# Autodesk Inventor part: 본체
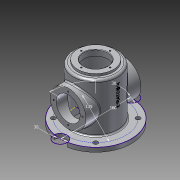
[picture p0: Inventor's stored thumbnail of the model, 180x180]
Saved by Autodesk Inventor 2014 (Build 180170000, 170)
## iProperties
Created: 2018-04
Part Number: 본체
Material: 알루미늄 6061
Document SubType Name: Modeling
Designer: NET
Density: 2.71 g/cm^3
Appearance: 알루미늄 - 평지
Mass: 1154.35 g
Surface Area: 1215.52 cm^2
Volume: 425.961 cm^3
Author: NET
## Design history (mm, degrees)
sketch "스케치1"
  geometry: L1 (-40, 65)-(-40, 60); L2 (-40, 60)-(-45, 60); L3 (-50, 55)-(-50, -68); L4 (-50, -68)-(0, -68); L5 (-40, 65)-(-27, 65); L6 (-27, 65)-(-27, 52); L7 (0, 65)-(0, -68); L8 (-27, 52)-(0, 52); A1 r 5 centre (-45, 55) between (-45, 60) and (-50, 55); 3 further points
  constraints: 16 end point, 5 point on line, 2 coincident, 2 horizontal, 2 perpendicular, 2 point on circle, 2 tangent, 1 centre point, 1 horizontal alignment, 1 parallel, 1 vertical
  dimensions: "d4" = 5 distance between parallel lines of L5 L2; "d5" = 133 distance between parallel lines of L4 L5; "d8" = 5 radius of A1; "d13" = 68 distance of L7.end point (0, 0); "d15" = 100 diameter of L3 L7; "d16" = 54 diameter of L6 L7; "d17" = 80 diameter of L1 L7; "d24" = 13 distance of L5.end L6.end
sketch "스케치2"
  geometry: L1 (-62, 0)-(62, 0); L2 (-62, 0)-(-62, 40); L3 (-62, 40)-(62, 40); L4 (62, 40)-(62, 0); 2 further points
  constraints: 8 end point, 2 perpendicular, 1 coincident, 1 horizontal, 1 midpoint, 1 vertical
  dimensions: "d22" = 124 distance of L2.end L3.end; "d23" = 80 diameter of L3 L1
revolve "회전3" stored, may be unused: angle "d25" = 90 deg
revolve "회전4" stored, may be unused: angle "d26" = 90 deg
sketch "스케치3"
  geometry: C1 r 50 at (0, 0) reference; C2 r 45 at (0, 0)
  constraints: 1 centre point, 1 coincident
  dimensions: "d27" = 90 diameter of C2
extrude "돌출1" cut sketch "스케치3" distance "d28" = 120; taper "d29" = 0 deg
fillet "모깎기1" dims "d30" = 3
sketch "스케치4"
  geometry: C1 r 40 at (0, 0) reference; C2 r 27 at (0, 0); 1 further point
  constraints: 1 centre point, 1 coincident, 1 vertical alignment
  dimensions: "d31" = 54 diameter of C2; "d34" = 32.5 distance of C1.centre point (0, 32.5)
extrude "돌출2" cut sketch "스케치4" stored distance "d32" = 120; taper "d33" = 0 deg
hole "구멍1" sketch "스케치4" diameter "d35" = 3.242; stored, may be unused: countersink angle "d39" = 90 deg, drill point angle "d41" = 118 deg; dims "d36" = 8, "d37" = 4, "d38" = 2, "d40" = 10
sketch "스케치5"
  geometry: C1 r 40 at (0, 0) reference; 1 further point
  constraints: 1 vertical alignment
  dimensions: "d45" = 32.5 distance of C1.centre point (0, 32.5)
hole "구멍2" sketch "스케치5" at (0, 32.5) diameter "d46" = 3.242; stored, may be unused: countersink angle "d50" = 90 deg, drill point angle "d52" = 118 deg; dims "d47" = 8, "d48" = 4, "d49" = 2, "d51" = 10
chamfer "모따기3" distance "d56" = 1; stored, may be unused: second distance "d57" = 2, angle "d58" = 45 deg
node "작업 평면1"
sketch "스케치6" dims "d89" = 135
  geometry: L1 (-47.73, 47.73)-(0, 0); L2 (0, 0)-(-80, 0); C1 r 50 at (0, 0) reference; C2 r 46 at (0, 0) reference; C3 r 15 at (0, 80); C4 r 15 at (0, -80); A1 r 80 centre (0, 0) between (0, 80) and (0, -80); 1 further point
  constraints: 4 end point, 3 centre point, 3 point on circle, 2 coincident, 2 vertical alignment, 1 horizontal, 3 other
  dimensions: "d60" = 160 diameter of A1; "d85" = 30 diameter of C3; "d86" = 30 diameter of C4; "d90" = 45 deg angle of L2 L1
  node "투영된 루프1"
extrude "바닥" join sketch "스케치6" distance "d64" = 10; taper "d65" = 0 deg
fillet "모깎기2" dims "d80" = 3
node "작업 평면2"
sketch "스케치8"
  geometry: L1 (0, -50)-(80, -50) reference; 2 further points
  constraints: 1 vertical alignment, 1 other
  dimensions: "d82" = 70 distance from line of L1 point (0, 20)
feature "엠보싱1" sketch "스케치8" dims "d83" = 0.5, "d84" = 0
extrude "돌출5" cut sketch "스케치6" distance "d87" = 10; taper "d88" = 0 deg
hole "구멍4" sketch "스케치6" diameter "d91" = 10; stored, may be unused: countersink angle "d95" = 90 deg, drill point angle "d97" = 118 deg; dims "d92" = 6, "d93" = 4, "d94" = 2, "d96" = 8
node "솔리드3"
pattern_circular "원형 패턴1" dims angle "d43" = 360 deg
mirror "대칭1"
pattern_circular "원형 패턴2" dims angle "d54" = 360 deg
pattern_circular "원형 패턴4" dims angle "d99" = 360 deg
